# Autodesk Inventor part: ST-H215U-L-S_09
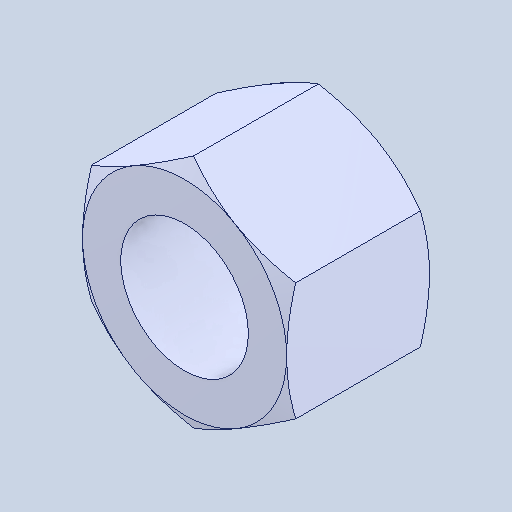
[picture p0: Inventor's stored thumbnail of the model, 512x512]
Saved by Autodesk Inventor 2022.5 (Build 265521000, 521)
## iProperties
Created: 2024-07
Part Number: ST-H215U-L-S_09
Material: 一般
Document SubType Name: Modeling
Designer: ImaoCorp
Density: 1 g/cm^3
Appearance: 既定
Author: ImaoCorp
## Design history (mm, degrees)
feature "ST-H215U-L-S_09"
node "ソリッド1"
